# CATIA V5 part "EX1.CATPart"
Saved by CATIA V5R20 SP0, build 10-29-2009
Part number: EX1
Bounding box of the stored display mesh (mm): x 0 to 50, y 0 to 50, z 0 to 10
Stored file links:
  E:\Nouveau dossier\tarek\mécaniquee\Catia\TP 0\EX1.CATPart
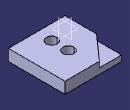
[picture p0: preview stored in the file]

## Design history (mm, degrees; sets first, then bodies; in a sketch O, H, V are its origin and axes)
Body1 (main body)
  Sketch1 on xy-plane, origin (0, 0, 0), H (1, 0, 0), V (0, 1, 0)
    line L1 (0, 0) -> (50, 0)
    line L2 (50, 0) -> (50, 50)
    line L3 (50, 50) -> (0, 50)
    line L4 (0, 50) -> (0, 0)
    length L3 = 50
    length L2 = 50
    horizontal: L1 H, L3 H
    vertical: L2 V, L4 V
  Pad1: profile Sketch1, direction (0, 0, 1), length 10
  Sketch2 on end face of Pad1, origin (0, 0, 10), H (1, 0, 0), V (0, 1, 0)
    line L1 (0, 0) -> (25, 13.2927)
    circle A1 centre (25, 13.2927) radius 5
    circle A2 centre (25, 28) radius 5
    radius A1 = 5
    radius A2 = 5
  Pocket1: profile Sketch2, direction (0, 0, -1), through (limit type 6)
  Sketch3 on end face of Pad1, origin (0, 0, 10), H (1, 0, 0), V (0, 1, 0)
    point P1 (0, 28)
    line L1 (0, 28) -> (19.79, 50)
    point P2 (19.79, 50)
    reference projected line E1 (0, 50) -> (0, 0) from edge [face of Pad1 from Sketch1.L4 | end face of Pad1]
    reference projected line E2 (0, 0) -> (50, 0) from edge [face of Pad1 from Sketch1.L1 | end face of Pad1]
    distance P2 E1 = 19.79
    distance E2 P1 = 28
    coincidence: P1 V
  Pocket2: profile Sketch3, direction (0, 0, -1), length 5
